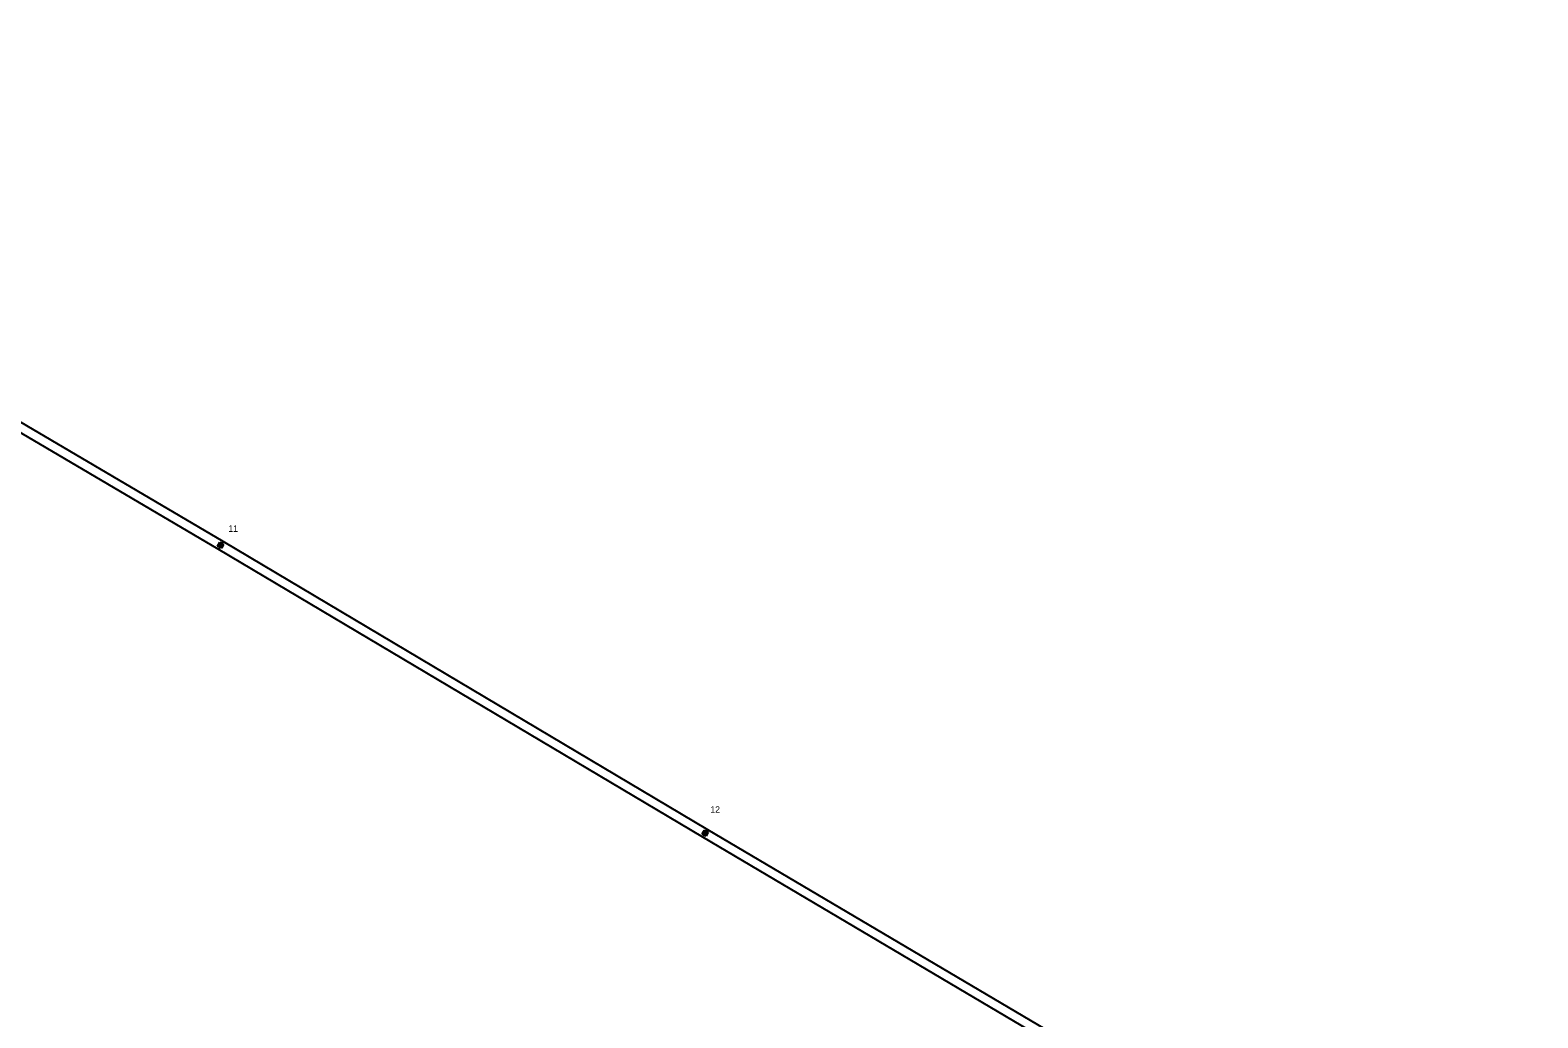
# Model space of a CAD drawing. Extents: x -545588 to -543214, y -1196037 to -1194452.
# Drawn here: x -544058.1 to -543648.2, y -1195769.1 to -1195500.7 of the extents above; entities that cross this region are included whole.
import ezdxf

# ---------------------------------------------------------------- set-up
doc = ezdxf.new("R2010")
doc.units = 0
for name, color, linetype in [('Vrstva 1', 7, 'Continuous'), ('Vrstva 13', 7, 'Continuous'), ('Vrstva 14', 7, 'Continuous'), ('Vrstva 2', 7, 'Continuous')]:
    doc.layers.add(name, color=color, linetype=linetype)

# ---------------------------------------------------------------- blocks, each defined once
blk = doc.blocks.new('VN470')
at = {"layer": 'Vrstva 2'}
for points in [[(-1.23, 1.22), (1.23, 1.22)], [(-1.23, -1.23), (-1.23, 1.22)], [(-0.92, 0.9), (0.92, 0.9)], [(-0.92, -0.95), (-0.92, 0.9)], [(-0.61, 0.61), (0.61, 0.61)], [(-0.61, -0.62), (-0.61, 0.61)], [(-0.31, -0.27), (-0.31, 0.34)], [(-0.31, 0.34), (0.31, 0.34)], [(0, 1.22), (0, 1.97)], [(0.31, 0.34), (0.31, -0.27)], [(0.61, 0.61), (0.61, -0.62)], [(0.92, 0.9), (0.92, -0.95)], [(1.23, 1.22), (1.23, -1.23)], [(1.23, -1.23), (-1.23, -1.23)], [(0.92, -0.95), (-0.92, -0.95)], [(0.61, -0.62), (-0.61, -0.62)], [(0.31, -0.27), (-0.31, -0.27)], [(0, -1.23), (0, -1.98)]]:
    blk.add_lwpolyline(points, dxfattribs=at)

msp = doc.modelspace()

# ---------------------------------------------------------------- linework, layer by layer
at = {"layer": 'Vrstva 1'}
for points in [[(-543649.39, -1195854.44), (-543751.62, -1195793.1), (-543875.2, -1195719.97), (-544006.92, -1195641.71), (-544142.24, -1195562.12), (-544281.11, -1195480), (-544421.5, -1195396.73), (-544557.6, -1195316.44), (-544689.64, -1195237.57), (-544834.28, -1195151.89), (-544970.6, -1195070.55), (-545089.61, -1194965.95)], [(-545087.98, -1194964.09), (-544969.35, -1195068.41), (-544833.03, -1195149.76), (-544688.41, -1195235.46), (-544556.36, -1195314.32), (-544420.24, -1195394.62), (-544279.84, -1195477.88), (-544141.02, -1195559.94), (-544005.67, -1195639.57), (-543873.94, -1195717.89), (-543750.35, -1195790.92), (-543648.17, -1195852.31)]]:
    msp.add_lwpolyline(points, dxfattribs=at)

# ---------------------------------------------------------------- block references
at = {"layer": 'Vrstva 13', "xscale": 0.5000000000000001}
for p, yscale, rotation in [((-544006.31, -1195640.68), 0.4999999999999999, 149.30919731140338), ((-543874.54, -1195718.89), 0.5000000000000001, 149.39949998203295)]:
    msp.add_blockref('VN470', p, dxfattribs=dict(at, yscale=yscale, rotation=rotation))

# ---------------------------------------------------------------- texts
at = {"layer": 'Vrstva 14'}
for s, p in [('11', (-544004.18, -1195637.04)), ('12', (-543873.14, -1195713.36))]:
    msp.add_text(s, height=1.75, dxfattribs=at).set_placement(p)

doc.saveas('drawing.dxf')
